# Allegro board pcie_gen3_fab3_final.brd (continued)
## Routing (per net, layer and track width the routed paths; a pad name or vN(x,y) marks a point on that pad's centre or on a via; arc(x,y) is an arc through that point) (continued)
LOAD1: length 88.6
  TOP w0.171: U3.1 19.45,246.42
  TOP w0.184: 106.47,246.42 R9.1 ; 106.47,246.42 19.45,246.42 ; 106.47,246.42 R10.1
LOAD2: length 108
  TOP w0.171: U4.1 18.72,227.37
  TOP w0.184: 105.85,227.34 79.01,227.34 arc(78.09,227.16) 77.3,226.63 arc(76.77,225.84) 76.59,224.91 76.59,222.57 arc(75.93,220.99) 74.35,220.33 65.28,220.33 arc(63.49,221.08) 62.74,222.87 62.74,224.88 arc(62.57,225.72) 62.1,226.44 arc(61.38,226.92) 60.53,227.09 48.57,227.09 arc(47.65,226.91) 46.88,226.39 arc(46.36,225.62) 46.18,224.7 46.18,222.62 arc(46.01,221.77) 45.53,221.06 arc(44.82,220.58) 43.97,220.41 29.86,220.41 arc(28.06,221.15) 27.32,222.95 27.32,224.83 arc(26.57,226.62) 24.78,227.37 18.72,227.37 ; 105.85,227.34 R11.1 ; 105.85,227.34 R12.1
PRIMARY_THRU: length 87.8
  TOP w0.171: 17.76,265.47 U1.1
  TOP w0.184: U2.1 84.76,265.44 84.76,265.47 17.76,265.47
R_T1_CONN: length 5.3
  TOP w0.184: R2.2 57,357.35 J2.B15
R_T1_EDGE: length 6.4
  TOP w0.184: R17.2 57.87,8.27 57.86,8.26 57.86,6.71 58.05,6.51 J7.B15
R_T2_CONN: length 5.7
  TOP w0.184: R1.2 54.61,356.35 J2.B16
R_T2_EDGE: length 6.4
  TOP w0.184: J7.B16 59.05,6.36 arc(59.07,6.49) 59.15,6.61 arc(59.22,6.72) 59.25,6.85 59.25,8.24 59.22,8.27 59.22,8.94 59.24,8.96 59.24,9.51 59.22,9.53 59.22,9.82 R18.2
R_T9_CONN: length 5.6
  TOP w0.184: J2.B31 56.67,341.35 R6.2
R_T9_EDGE: length 5.3
  TOP w0.184: R19.2 73.82,7.53 arc(73.84,7.31) 73.9,7.11 73.99,6.89 arc(74.03,6.75) 74.05,6.61 J7.B31
R_T10_CONN: length 6
  TOP w0.184: J2.B32 54.26,340.35 R5.2
R_T10_EDGE: length 5.5
  TOP w0.184: R20.2 74.95,7.9 75.31,7.54 75.31,6.74 75.05,6.48 J7.B32
R_T11_CONN: length 4.7
  TOP w0.184: J2.A30 71.46,342.35 R8.1
R_T11_EDGE: length 6.3
  BOTTOM w0.184: J7.A30 73.05,6.37 73.2,6.53 73.2,7.09 73.32,7.21 R28.1
R_T12_CONN: length 4.7
  TOP w0.184: R7.1 69.46,343.35 J2.A29
R_T12_EDGE: length 6.3
  BOTTOM w0.184: R27.1 72.05,8.21 arc(71.97,8.18) 71.94,8.1 71.94,6.52 72.05,6.41 J7.A29
R_T17_EDGE: length 6.7
  BOTTOM w0.152: 61.14,6.55 61.16,6.57 ; J7.A18 61.05,3.79
  BOTTOM w0.184: 61.14,6.55 61.05,6.45 61.05,3.79 ; 61.16,6.57 R26.1
R_T18_EDGE: length 6.8
  BOTTOM w0.152: J7.A17 60.05,3.79
  BOTTOM w0.184: R25.1 59.77,10.12 59.75,10.1 59.75,6.62 60.05,6.33 60.05,3.79
SECONDARY1: length 138.4
  TOP w0.171: U6.1 18.19,189.27 ; 105.86,189.27 U7.1
  TOP w0.184: 105.86,189.27 99.19,189.27 99.19,189.27 82.84,189.27 arc(81.86,189.07) 81.04,188.52 80.93,188.42 arc(80.38,187.59) 80.19,186.62 80.19,181.33 arc(80.19,181.16) 80.18,181 80.18,177.04 arc(79.99,176.07) 79.44,175.25 79.36,175.17 arc(78.53,174.62) 77.56,174.42 65.86,174.42 arc(64.95,174.6) 64.17,175.12 arc(63.66,175.89) 63.47,176.81 63.47,187.68 arc(63.28,188.64) 62.74,189.46 arc(61.92,190) 60.96,190.2 46.8,190.2 arc(45.84,190) 45.03,189.46 arc(44.48,188.65) 44.29,187.69 44.29,178.35 arc(44.27,178.09) 44.19,177.85 44.09,177.6 arc(44.08,177.56) 44.07,177.51 44.07,177.49 43.8,177.22 arc(43.5,177.01) 43.14,176.94 27.74,176.94 arc(27.26,177.04) 26.86,177.31 arc(26.59,177.71) 26.49,178.19 26.49,186.73 arc(25.75,188.52) 23.95,189.27 18.19,189.27
SECONDARY2: length 100
  TOP w0.171: U9.1 105.87,154.67 ; 18.19,154.67 U8.1
  TOP w0.184: 18.19,154.67 40.89,154.67 arc(41.84,154.86) 42.65,155.4 arc(43.19,156.21) 43.38,157.17 43.38,159.53 arc(43.56,160.43) 44.07,161.19 arc(44.83,161.7) 45.72,161.87 69.93,161.87 arc(71.52,161.21) 72.19,159.61 72.19,157.36 arc(72.93,155.56) 74.73,154.82 105.73,154.82 arc(105.83,154.77) 105.87,154.67
SECONDARY3: length 90.8
  TOP w0.171: U10.1 18.19,135.62 ; 100.08,135.62 U11.1
  TOP w0.184: 18.19,135.62 25.41,135.62 arc(27.21,134.88) 27.95,133.08 27.95,132.56 arc(28.05,132.08) 28.32,131.68 29.03,130.97 arc(29.82,130.44) 30.75,130.26 55.83,130.26 arc(57.62,131) 58.37,132.8 58.37,134.25 arc(58.77,135.22) 59.74,135.62 100.08,135.62
SHORT: length 43.4
  TOP w0.171: U5.1 21.09,208.32
  TOP w0.184: 21.09,208.32 63.43,208.32
T3_EDGE: length 47.3
  TOP w0.171: 25.34,14.65 AICJ7B19.1
  TOP w0.184: 25.34,14.65 36.42,14.65 arc(36.93,14.86) 37.15,15.37 arc(37.37,15.9) 37.9,16.12 39.36,16.12 arc(39.54,16.09) 39.7,15.98 arc(39.8,15.83) 39.84,15.64 39.84,15.39 arc(40.08,14.8) 40.66,14.56 55.53,14.56 arc(56.5,14.37) 57.32,13.82 60.93,10.21 arc(61.25,9.82) 61.48,9.39 61.76,8.72 61.98,8.19 arc(62.03,8.02) 62.05,7.84 62.05,7.75 arc(62.03,7.69) 62,7.64 arc(61.96,7.58) 61.95,7.52 61.95,7.05 61.95,7.02 61.95,6.94 62.05,6.85 J7.B19
T4_EDGE: length 47.3
  TOP w0.171: 35.88,30.27 AICJ7B20.1
  TOP w0.184: 35.88,30.27 35.88,26.66 arc(35.89,26.43) 35.92,26.21 arc(36.17,25.48) 36.62,24.86 42.46,19.02 arc(43.29,18.47) 44.26,18.28 56.82,18.28 arc(57.79,18.08) 58.61,17.53 62.3,13.84 arc(62.85,13.02) 63.05,12.04 63.05,7.53 63.14,7.43 63.14,6.94 63.05,6.85 J7.B20
T5_EDGE: length 47.3
  TOP w0.171: 55.65,42.89 AICJ7B23.1
  TOP w0.184: 55.65,42.89 55.65,24.41 arc(55.78,23.78) 56.14,23.24 arc(56.68,22.88) 57.31,22.75 61.3,22.75 arc(62.76,22.14) 63.37,20.67 63.37,18.6 63.85,17.88 63.93,17.7 arc(64.03,17.47) 64.16,17.26 64.43,16.85 arc(64.56,16.64) 64.67,16.41 65.85,13.55 arc(66,13.08) 66.05,12.58 66.05,7.45 65.96,7.36 65.96,7.01 66.05,6.93 J7.B23
T6_EDGE: length 47.3
  TOP w0.171: 75.43,46.45 AICJ7B24.1
  TOP w0.184: J7.B24 67.05,6.5 67.16,6.61 67.16,16.96 67.18,16.96 67.18,22.6 arc(67.93,24.39) 69.72,25.14 arc(70.87,25.61) 71.34,26.76 71.34,29.01 arc(71.39,29.52) 71.55,30.01 75.17,38.49 arc(75.32,38.96) 75.36,39.46 75.36,43.28 75.43,43.28 75.43,46.45
T7_EDGE: length 47.3
  TOP w0.171: 89.42,23.13 AICJ7B27.1
  TOP w0.184: 89.42,23.13 86.73,23.14 85.39,23.14 arc(84.56,23.3) 83.87,23.77 arc(83.4,24.47) 83.23,25.29 83.23,27.51 arc(82.87,28.4) 81.98,28.76 80.73,28.76 arc(78.94,28.02) 78.19,26.22 78.19,23.87 arc(78.16,23.65) 78.15,23.42 78.15,23.3 arc(77.96,22.33) 77.41,21.5 77.3,21.4 arc(76.48,20.85) 75.51,20.65 71.04,20.65 arc(70.66,20.58) 70.34,20.36 arc(70.12,20.04) 70.05,19.66 70.05,8.12 69.98,7.84 69.97,7.84 69.97,7.79 69.8,7.07 69.82,7.03 69.89,6.91 arc(70.01,6.65) 70.05,6.37 J7.B27
T8_EDGE: length 47.3
  TOP w0.171: 109.22,14.65 AICJ7B28.1
  TOP w0.184: J7.B28 71.05,6.18 arc(71.1,6.68) 71.24,7.15 72.32,9.77 arc(72.4,9.94) 72.49,10.11 72.52,10.16 arc(72.92,10.55) 73.47,10.7 84.23,10.7 arc(85.11,11.06) 85.48,11.94 85.48,12.17 arc(85.67,13.11) 86.21,13.92 arc(87.01,14.46) 87.96,14.65 109.22,14.65
T13_EDGE: length 47.3
  BOTTOM w0.171: 100.24,21.82 AICJ7A26.1
  BOTTOM w0.184: 100.24,21.82 100.24,17.37 arc(100.05,16.4) 99.5,15.58 97.71,13.79 arc(96.88,13.24) 95.91,13.04 71.66,13.04 arc(70.72,12.85) 69.92,12.32 arc(69.38,11.52) 69.2,10.58 69.2,6.62 arc(69.18,6.55) 69.14,6.5 69.14,6.49 arc(69.11,6.44) 69.09,6.37 69.09,3.49 J7.A26
T14_EDGE: length 47.3
  BOTTOM w0.171: 84.02,35.57 AICJ7A25.1
  BOTTOM w0.184: J7.A25 68.05,6.81 68.02,6.84 68.02,7.28 68.05,7.31 68.05,14.68 arc(68.79,16.48) 70.59,17.22 82.97,17.22 arc(83.19,17.25) 83.39,17.34 83.48,17.4 arc(83.73,17.6) 83.91,17.87 83.93,17.93 arc(83.97,18.04) 83.99,18.17 83.99,30.88 83.98,30.88 84.02,31.51 84.02,35.57
T15_EDGE: length 47.3
  BOTTOM w0.171: 64.78,31.13 AICJ7A22.1
  BOTTOM w0.184: J7.A22 65.05,6.09 65.27,7.03 65.27,7.88 65.05,8.28 65.05,19.46 arc(65.79,21.26) 67.59,22 73.28,22 arc(75.08,22.75) 75.82,24.54 75.82,28.59 arc(75.08,30.39) 73.28,31.13 64.78,31.13
T16_EDGE: length 47.3
  BOTTOM w0.171: 44.19,40.67 AICJ7A21.1
  BOTTOM w0.184: J7.A21 64.09,3.49 64.09,6.42 63.92,6.59 arc(63.83,7.08) 63.55,7.49 arc(63.3,7.81) 63.15,8.19 arc(63.11,8.39) 63.09,8.59 63.09,12.26 arc(62.9,13.24) 62.35,14.06 48.72,27.69 arc(47.89,28.24) 46.92,28.44 46.73,28.44 arc(44.94,29.18) 44.19,30.98 44.19,40.67
TEST3_CONN: length 45.7
  TOP w0.171: 48.26,387.65 J2B19.1
  TOP w0.184: 48.26,387.65 48.26,382.04 48.23,382.04 48.23,380.14 arc(48.38,379.41) 48.79,378.79 49.15,378.43 arc(49.41,378.04) 49.5,377.58 49.5,375.99 arc(49.31,375.02) 48.76,374.2 48.6,374.04 arc(48.35,373.66) 48.26,373.21 48.26,372.73 arc(48.45,371.76) 49,370.93 50.73,369.21 arc(51.04,368.83) 51.28,368.39 51.42,368.03 arc(51.53,367.69) 51.56,367.34 51.56,356.61 arc(51.61,356.38) 51.74,356.17 51.93,355.99 arc(52.41,355.67) 52.98,355.55 54.17,355.55 arc(54.17,355.55) 54.17,355.55 55.78,355.57 arc(56.32,355.51) 56.84,355.35 57,355.27 arc(57.26,355.14) 57.51,354.97 59.1,353.76 arc(60.66,353.46) J2.B19
TEST4_CONN: length 45.7
  TOP w0.171: 31.19,379.53 J2B20.1
  TOP w0.184: J2.B20 54.01,352.35 arc(53.03,352.55) 52.21,353.1 46.89,358.42 arc(46.57,358.8) 46.34,359.24 46.18,359.62 arc(46.1,359.9) 46.07,360.18 46.07,361.34 arc(46.01,361.79) 45.85,362.21 37.59,377.53 37.04,378.57 36.73,379.03 arc(36.53,379.25) 36.27,379.41 36.12,379.47 arc(35.98,379.51) 35.83,379.53 31.19,379.53
TEST5_CONN: length 45.7
  TOP w0.171: 31.19,359.35 J2B23.1
  TOP w0.184: 31.19,359.35 35.67,359.35 arc(35.69,359.35) 35.71,359.35 36.16,359.36 arc(36.17,359.36) 36.18,359.36 36.22,359.36 arc(36.67,359.46) 37.06,359.71 arc(37.32,360.1) 37.41,360.55 37.41,361.99 arc(37.8,362.95) 38.76,363.35 39.64,363.35 arc(41.22,362.69) 41.87,361.11 41.87,353.27 arc(41.89,353.06) 41.95,352.86 arc(42.03,352.71) 42.11,352.57 42.43,352.1 arc(42.58,351.9) 42.75,351.71 43.13,351.33 arc(43.51,351.01) 43.95,350.78 44.38,350.6 arc(44.78,350.48) 45.2,350.44 57.23,350.44 arc(58,350.34) 58.74,350.08 arc(58.89,349.95) 59.04,349.83 arc(59.65,349.48) 60.34,349.36 arc(61.29,349.36) J2.B23
TEST6_CONN: length 45.7
  TOP w0.171: 15.74,347.21 J2B24.1
  TOP w0.184: 15.74,347.21 29.64,347.21 arc(30.14,347.26) 30.61,347.4 31.44,347.75 arc(31.54,347.78) 31.63,347.81 32.2,347.95 32.7,348.16 arc(33.18,348.31) 33.67,348.35 J2.B24
TEST7_CONN: length 45.7
  TOP w0.171: 22.95,328.69 J2B27.1
  TOP w0.184: 22.95,328.69 26.64,328.69 arc(26.7,328.69) 26.77,328.69 arc(27.11,328.74) 27.44,328.84 27.88,329.01 arc(27.9,329.02) 27.93,329.03 27.95,329.03 27.95,329.07 30.93,330.39 arc(30.94,330.39) 30.96,330.4 arc(30.97,330.41) 30.98,330.42 45.6,342.15 45.61,342.15 46.66,343.12 46.66,343.13 49.65,344.7 49.65,344.71 52.54,345.3 52.58,345.3 52.8,345.34 arc(52.83,345.34) 52.86,345.35 52.89,345.35 53.03,345.35 53.08,345.35 arc(53.08,345.35) 53.08,345.35 J2.B27
TEST8_CONN: length 45.7
  TOP w0.171: 38.15,317.4 J2B28.1
  TOP w0.184: 38.15,317.4 38.15,323.6 arc(38.89,325.39) 40.69,326.14 45.21,326.14 arc(46.18,326.33) 47.01,326.88 47.62,327.49 arc(48.17,328.32) 48.36,329.29 48.36,340.45 arc(49.11,342.25) 50.9,342.99 56.71,342.99 arc(58.16,343.09) 59.58,343.43 arc(60.06,343.79) J2.B28
TEST13_CONN: length 45.7
  TOP w0.171: 95.71,327.72 J2A26.1
  TOP w0.184: 95.71,327.72 78.51,327.72 arc(77.54,327.91) 76.71,328.47 75.72,329.45 arc(75.17,330.28) 74.98,331.25 74.98,343.58 arc(74.9,343.97) 74.66,344.29 74.39,344.53 arc(74.2,344.61) 73.99,344.63 71.13,344.63 70.09,344.62 69.56,344.47 arc(68.77,344.57) 68.27,345.2 arc(67.7,346.03) J2.A26
TEST14_CONN: length 45.7
  TOP w0.171: 101.68,346.42 J2A25.1
  TOP w0.184: J2.A25 67.25,347.35 arc(67.89,347.48) 68.43,347.84 arc(68.69,348.02) 69,348.08 80.61,348.08 arc(81.59,347.88) 82.41,347.33 82.65,347.1 arc(82.86,346.84) 83.01,346.55 83.25,345.98 arc(83.33,345.7) 83.36,345.4 83.36,343.98 arc(83.55,343.03) 84.09,342.22 arc(84.89,341.69) 85.84,341.5 92.7,341.5 arc(93.23,341.6) 93.69,341.91 arc(93.99,342.36) 94.1,342.89 94.1,343.88 arc(94.84,345.67) 96.64,346.42 101.68,346.42
TEST15_CONN: length 45.7
  TOP w0.171: 104.75,366.37 J2A22.1
  TOP w0.184: J2.A22 80.27,350.35 arc(80.41,350.38) 80.53,350.46 83.01,352.94 88.35,357.65 arc(88.6,357.9) 88.8,358.17 90.06,360.1 arc(90.21,360.31) 90.39,360.51 95.5,365.62 arc(96.33,366.17) 97.3,366.37 104.75,366.37
TEST16_CONN: length 45.7
  TOP w0.171: 90.09,381.58 J2A21.1
  TOP w0.184: J2.A21 66.2,351.35 arc(67.17,351.55) 68,352.1 68.73,352.83 73.94,355.58 arc(74.73,356.25) 75.02,357.25 78.56,367.53 79.67,370.74 arc(79.87,371.48) 79.94,372.24 79.94,374.81 arc(80.01,375.41) 80.22,375.97 81.82,378.96 arc(82.03,379.18) 82.33,379.27 82.46,379.27 arc(82.9,379.5) 83.29,379.82 84.32,380.86 arc(85.15,381.41) 86.12,381.6 88.13,381.6 89.18,381.59 89.18,381.58 90.09,381.58
TEST17_CONN: length 2
  TOP w0.184: R4.1 67.7,354.7 arc(67.26,354.42) J2.A18
TEST18_CONN: length 6.5
  TOP w0.184: R3.1 70.97,356.35 68.83,356.35 arc(68.39,356.27) 68.01,356.04 67.69,355.73 arc(67.25,355.44) 66.74,355.35 J2.A17

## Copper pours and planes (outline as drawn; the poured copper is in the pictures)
GND_BASELINE on TOP: 63.69,5.6 63.69,9.24 61.4,9.24 61.4,5.62 59.69,5.62 59.69,9.24 57.4,9.24 57.4,5.63 54.69,5.63 54.69,9.24 52.4,9.24 52.4,5.66 41.69,5.66 41.69,9.24 2.36,9.24 1.11,10.11 0.64,11.56 0.64,73.15 1.34,74.86 3.05,75.56 123.95,75.56 125.59,74.92 126.36,73.33 126.36,11.38 125.83,10.04 124.64,9.24 69.4,9.24 69.4,5.62 67.69,5.62 67.69,9.24 65.4,9.24 65.4,5.6 ; 2 cut-outs
GND_BASELINE on TOP, BOTTOM, LAYER3: 3.05,79.38 1.34,80.08 0.64,81.79 0.64,412.24 1.34,413.95 3.05,414.65 123.95,414.65 125.66,413.95 126.36,412.24 126.36,81.79 125.66,80.08 123.95,79.38
GND_BASELINE on BOTTOM: 41.69,8.4 41.59,8.53 41.47,8.64 41.47,8.97 40.99,8.97 40.59,9.1 40.18,9.14 3.05,9.14 1.34,9.85 0.64,11.56 0.64,73.15 1.34,74.86 3.05,75.56 123.95,75.56 125.66,74.86 126.36,73.15 126.36,11.56 125.66,9.85 123.95,9.14 111.83,9.14 111.83,9.28 86.19,9.28 86.19,9.14 77.01,9.14 76.6,9.1 76.21,8.97 75.53,8.97 75.53,8.44 75.22,7.87 75.11,7.24 75.4,6.75 75.41,5.6 54.69,5.6 54.69,8.61 53.49,8.87 52.39,8.31 52.39,7.5 52.4,5.6 41.69,5.6 ; 5 cut-outs
GND_BASELINE on LAYER2: 41.69,8.4 41.02,8.95 40.18,9.14 3.05,9.14 1.34,9.85 0.64,11.56 0.64,73.15 1.34,74.86 3.05,75.56 123.95,75.56 125.66,74.86 126.36,73.15 126.36,11.56 125.66,9.85 123.95,9.14 77.01,9.14 75.79,8.57 75.46,7.27 75.4,5.71 75.4,5.66 75.45,5.66 75.46,5.65 75.46,5.61 75.45,5.61 54.73,5.61 54.69,5.64 54.69,8.26 53.63,8.91 52.46,8.49 52.4,8.44 52.4,5.61 41.78,5.61 41.69,5.7 ; 2 cut-outs
GND_BASELINE on LAYER2: 3.05,79.38 1.34,80.08 0.64,81.79 0.64,412.24 1.34,413.95 3.05,414.65 123.95,414.65 125.51,414.09 126.33,412.65 126.33,81.38 125.51,79.94 123.95,79.38
GND_BASELINE on LAYER3: 41.69,8.4 41.02,8.95 40.18,9.14 3.05,9.14 1.34,9.85 0.64,11.56 0.64,73.15 1.34,74.86 3.05,75.56 123.95,75.56 125.66,74.86 126.36,73.15 126.36,11.56 125.66,9.85 123.95,9.14 77.01,9.14 75.79,8.57 75.46,7.27 75.4,5.62 75.4,5.61 54.72,5.61 54.69,5.64 54.69,8.26 53.63,8.91 52.46,8.49 52.4,8.44 52.4,5.61 41.78,5.61 41.69,5.7 ; 2 cut-outs

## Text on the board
BOTTOM: 4 | G45493-003 | G45491-003
Ref Des/Silkscreen Bottom: A1 | A11 | A12 | A32 | AICJ7A21 | AICJ7A22 | AICJ7A25 | AICJ7A26 | AICJ7B24 | U1 | J2B24 | J2B23 | J2B19 | J2 | U8 | U10 | SHORT | PRIMARY THRU | LOAD 2 | SECONDARY 3 | SECONDARY 1 | SECONDARY 2 | LOAD 1 | U11 | U9
User.Comments: 35 | 15
Ref Des/Silkscreen Top: AICJ7B23 | J2B24 | J2B27 | J2B20 | J2B23 | J2B28 | J2A21 | J2A26 | J2A25 | J2A22 | J2B19 | 3.938 | 3.574 | 5.447 | 3.458 | 3.490 | 1.730 | Fmin .300 Fmax 1.240 | Fmin 5.150 Fmax 20 | 4.250 | Fmin 1.240 Fmax 5.150 | SHORT | PRIMARY THRU | LOAD 1 | SECONDARY 3 | SECONDARY 2 | SECONDARY 1 | LOAD 2 | HILLE_GREEN
DIMENSION: -A- | -B- | .250 | 2 PLACES | 8 PLACES | .500 | 11 | SEE DETAIL B page 2 | 9 | SEE DETAIL A 4 places | Suggested panel usage with 7" off axis rotation. | artwork sheet 13 OF 13 | FOR REFERENCE ONLY
User.24: -A- | -B- | 9 | 12
User.33: * | 1 | 01
User.35: .331 MIN | 8.40 MIN | 12.15 | .478 | .051 | 1.30 | .394 | 10 | .059 | 22.15 | 1.5 | .872 | .787 | 20 | .037 | 0.95 | .075+/-.002 | 1.9+/-.06 | .039 | 1 | .020 x 45 TYP | 8.51 | .335 | 0.5 | FULL RADIUS 1X | NELCO 13 SI | (PLATED 1/2oz Cu) | (GND 1 oz Cu) | LAYER 1 | LAYER 2 | LAYER 3 | LAYER 4 | (GND 1oz Cu) | (NELCO 13) | CORE | OVERALL BOARD THICKNESS SPECIFICATION | TOTAL- | ADJUST CORE THICKNESS TO ACHIEVE | THICKNESS | .0019  MIN ,0014 | .003   MAX ,0048 | .0014  +/- .0002 | .0012  +/- .0002 | .003   MAX .0048 | .00190 MIN .0014 | .062 +.006 -.006 | TOLERANCE | 12 of | 13 | .062+.006-.006 | [1.30] | ACROSS PADS | +/- .008 | 10. CONTROLLED IMPEDANCE 42.5 OHMS +/- 5% 7.25 MIL TRACE LAYERS 1 & 4. | 11  MARK PANEL NUMBER IN APPROXIMATE AREA SHOWN. AVOID SILKSCREEN  OVER ANY TRACES | 12  SURFACE FINISH:IMMERSION SILVER. | 9 GOLD FINGERS PER DETAIL A. PLATE MINIMUM 20 MIRCRO-INCHES GOLD OVER | NOTES: UNLESS OTHERWISE SPECIFIED: | 1. PART NUMBER IS PARENT ITEM IDENTIFICATION NUMBER ON | 2. THIS DRAWING ALSO EXISTS ON ELECTRONIC MEDIA. | 4  THE CENTER OF THESE TWO HOLES ESTABLISH DATUM -A-. | 5  DATUM -B- IS ESTABLISHED PERPENDICULAR TO DATUM -A- THROUGH | 6. DIMENSIONING AND TOLERANCING PER AMSE Y14.5 | 7  FAB VENDOR MAY ADD COPPER THIEVING AS NEEDED ON OUTER LAYERS | 8  THESE HOLES MAY BE PLATED SHUT OR SOLDER FILLED. | 3  VENDOR TO USE BLUE SOLDERMASK UNDER WHITE INK | MINIMUM 150 MICRO-INCHES OF NICKEL. | ENGINEERING BILL OF MATERIAL. | THE CENTER OF THIS HOLE. | COPPER THIEVING NO CLOSER THAN O.100" TO ANY COPPER FEATURE OR LAYER WINDOW. | W | SCALE: NONE | 70 +/-3 | 4 LAYER STACKUP | LAYER STACKING | 9 | DETAIL-B | VIEW B-B
User.36: PB,DOC,EMSD,PCIE G3,FAB3
User.37: 12
User.45: INTERNAL LAYER #6 | INTERNAL LAYER #5 | 6 | 7 | 01 | Initial release of Fab 3 | FIGURE | SIZE | 10.0 | 14.0 | 24.0 | 28.0 | 70.0 | 25.0 | 93.0 | 156.0 | 250.0 | DRILL CHART: TOP to BOTTOM | ALL UNITS ARE IN MILS | TOLERANCE | +4.0/-8.0 | +3.0/-3.0 | PLATED | NON-PLATED | QTY | 1431 | 186 | 31 | 64 | 124 | 16 | 2 | 9 | 2 places | 4 PLACES | DO NOT SCALE | CENTER POINT OF PERF TAB DIMENSIONED ON MAIN DRAWING | DRILL DATA IN DRILL FILE FOR ALL PERF TAB DRILLS. | B. Hill | J.HILDEBRAND | A. Toomey | 012611 | 102611 | 101110 | 1:1 | 11 of 12 | B | 8 | PB,DOC,EMSD,PCIE G3,FAB3 | PRIMARY SIDE VIEW | DETAIL A | G45487
